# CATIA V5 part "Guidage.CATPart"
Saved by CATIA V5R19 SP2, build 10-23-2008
Part number: Guidage
Bounding box of the stored display mesh (mm): x 499.397 to 540.397, y 25.534 to 65.534, z 290 to 310
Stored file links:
  C:\Users\Romain\Documents\IFMA\2A\cours\S3\Projet CFAO-IAO\IAO\Catia\Guidage.CATPart
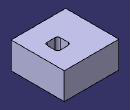
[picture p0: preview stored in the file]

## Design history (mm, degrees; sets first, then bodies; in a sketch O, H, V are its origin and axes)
Body1 (main body)
  Plane1: stored without definition
  Sketch1 on Plane1, origin (0, 0, 290), H (1, 0, 0), V (0, 1, 0)
    line L1 (499.3965, 65.5337) -> (499.3965, 25.5337)
    line L2 (499.3965, 25.5337) -> (540.3965, 25.5337)
    line L3 (540.3965, 25.5337) -> (540.3965, 65.5337)
    line L4 (540.3965, 65.5337) -> (499.3965, 65.5337)
    length L4 = 41
    length L3 = 40
    vertical: L1 V, L3 V
    horizontal: L2 H, L4 H
  Pad1: profile Sketch1, direction (0, 0, 1), length 20
  Sketch2 on end face of Pad1, origin (0, 0, 310), H (1, 0, 0), V (0, 1, 0)
    line L1 (520.3965, 50.5337) -> (530.3965, 50.5337)
    line L2 (530.3965, 50.5337) -> (530.3965, 40.5337)
    line L3 (530.3965, 40.5337) -> (520.3965, 40.5337)
    line L4 (520.3965, 40.5337) -> (520.3965, 50.5337)
    reference projected line E1 (540.3965, 65.5337) -> (499.3965, 65.5337) from edge [face of Pad1 from Sketch1.L4 | end face of Pad1]
    reference projected line E2 (499.3965, 65.5337) -> (499.3965, 25.5337) from edge [face of Pad1 from Sketch1.L1 | end face of Pad1]
    length L1 = 10
    length L4 = 10
    distance E1 L1 = 15
    distance E2 L4 = 21
    horizontal: L1 H, L3 H
    vertical: L2 V, L4 V
  Pocket1: profile Sketch2, direction (0, 0, -1), through (limit type 3)
  Fillet1: radius 2, on edge [face of Pocket1 from Sketch2.L2 | face of Pocket1 from Sketch2.L3]; edge [face of Pocket1 from Sketch2.L1 | face of Pocket1 from Sketch2.L2]; edge [face of Pocket1 from Sketch2.L4 | face of Pocket1 from Sketch2.L1]; edge [face of Pocket1 from Sketch2.L3 | face of Pocket1 from Sketch2.L4]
